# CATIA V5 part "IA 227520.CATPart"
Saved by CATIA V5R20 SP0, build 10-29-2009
Part number: IA 227520
Revision: ANY
Definition: UNKNOWN
Nomenclature: IA 227520
Source: Unknown
Bounding box of the stored display mesh (mm): x -1.102 to 1.102, y -0.001 to 7.75, z -1.102 to 1.102
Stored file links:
  C:\Users\Utente\Desktop\IO LAVORO\3D X SITO CF\CUMSA\3D files FA\FA 042212-20\IA 227520.CATPart

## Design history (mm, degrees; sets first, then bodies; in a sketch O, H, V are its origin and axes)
Body1 "Cortar-Extruir3" (main body)
  Solid1: solid without history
